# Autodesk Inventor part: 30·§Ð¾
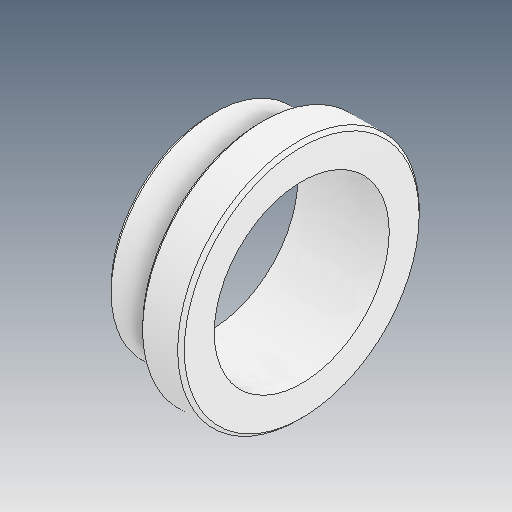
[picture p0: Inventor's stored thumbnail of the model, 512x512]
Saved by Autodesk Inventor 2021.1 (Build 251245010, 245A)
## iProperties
Created: 2021-05
Part Number: 30·§Ð¾
Material: Ogólny
Document SubType Name: Modeling
Designer: user
Density: 1 g/cm^3
Appearance: Domyślna
Author: user
Revision Number: ÈÎºÎ
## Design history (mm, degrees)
feature "ÊäÈë1"
node "Bryła1"
